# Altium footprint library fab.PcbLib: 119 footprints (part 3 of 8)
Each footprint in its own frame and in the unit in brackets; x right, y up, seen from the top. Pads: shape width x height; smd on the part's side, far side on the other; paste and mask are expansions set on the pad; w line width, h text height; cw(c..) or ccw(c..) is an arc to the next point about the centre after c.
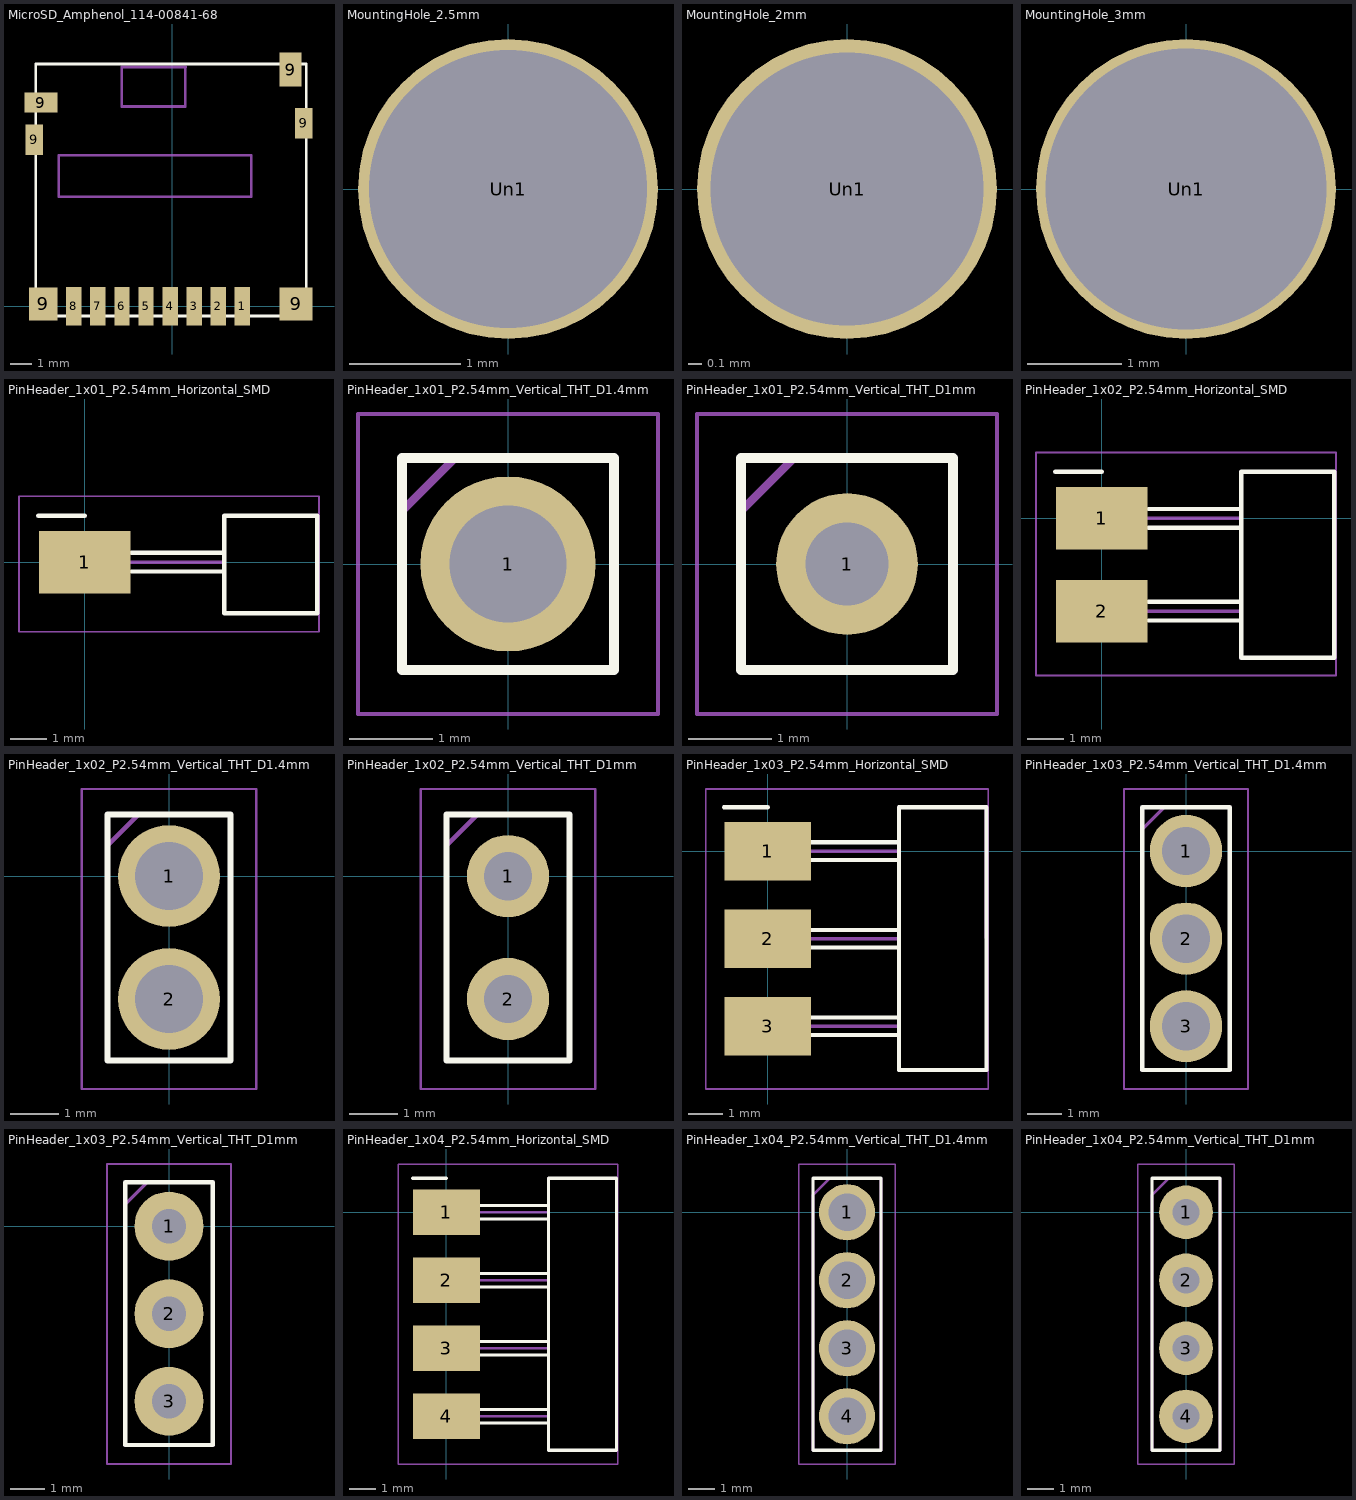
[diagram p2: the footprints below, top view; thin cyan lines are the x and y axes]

## MicroSD_Amphenol_114-00841-68 [mm]
pads (14):
  rect 0.7x1.75 smd: 1(3.2,0) 2(2.1,0) 3(1,0) 4(-0.1,0) 5(-1.2,0) 6(-2.3,0) 7(-3.4,0) 8(-4.5,0)
  rect 0.8x1.4 smd: 9(-6.3,7.6) 9(6,8.35)
  rect 1.5x0.9 smd: 9(-6,9.3)
  rect 1.3x1.5 smd: 9(-5.9,0.1)
  rect 1x1.55 smd: 9(5.4,10.8)
  rect 1.5x1.5 smd: 9(5.65,0.1)
F.SilkS:
  lines w0.12: -6.23,-0.45 -6.23,11.06 6.12,11.06 6.12,-0.45 -6.23,-0.45
F.Fab:
  lines w0.12: 0.6,10.92 0.6,9.12 -2.3,9.12 -2.3,10.92 0.61,10.92 ; -5.18,5 -5.18,6.89 3.61,6.89 3.61,5 -5.18,5
  text "%R" at -0.393,1.706 h1
  text "CLEAR" at -1.201,9.848 h0.5
  text "KEEP CLEAR" at -1.647,5.808 h0.5

## MountingHole_2.5mm [mm]
pads (1):
  round 2.7 hole 2.5: Un1(0,0)

## MountingHole_2mm [mm]
pads (1):
  round 2.2 hole 2: Un1(0,0)

## MountingHole_3mm [mm]
pads (1):
  round 3.2 hole 3: Un1(0,0)

## PinHeader_1x01_P2.54mm_Horizontal_SMD [mm]
pads (1):
  rect 2.5x1.7 smd: 1(0,0)
F.SilkS:
  lines w0.12: -1.27,1.27 0,1.27 ; 1.27,-0.254 3.81,-0.254 ; 1.27,0.254 3.81,0.254 ; 3.81,-1.397 6.35,-1.397 6.35,1.27 3.81,1.27 3.81,-1.397
F.CrtYd:
  lines w0.05: -1.8,-1.9 6.4,-1.9 6.4,1.8 -1.8,1.8 -1.8,-1.9
F.Fab:
  lines w0.1: -0.635,-0.254 -0.635,0.254 ; -0.635,0 3.81,0 ; 3.8,1.27 3.81,-1.4 6.36,-1.4 6.34,1.27 3.8,1.27
  text "%R" at 2.794,-0.393 h1

## PinHeader_1x01_P2.54mm_Vertical_THT_D1.4mm [mm]
pads (1):
  round 2.1 hole 1.4: 1(0,0)
F.SilkS:
  lines w0.12: -1.27,-1.27 1.27,-1.27 1.27,1.27 -1.27,1.27 -1.27,-1.27
F.CrtYd:
  lines w0.05: -1.8,-1.8 -1.8,1.8 1.8,1.8 1.8,-1.8 -1.8,-1.8
F.Fab:
  lines w0.1: -1.27,-1.27 1.27,-1.27 1.27,1.27 -0.635,1.27 -1.27,0.635 -1.27,-1.27
  text "%R" at 0.294,0.207 h1

## PinHeader_1x01_P2.54mm_Vertical_THT_D1mm [mm]
pads (1):
  rrect100% 1.7x1.7 hole 1: 1(0,0)
F.SilkS:
  lines w0.12: -1.27,-1.27 -1.27,1.27 1.27,1.27 1.27,-1.27 -1.27,-1.27
F.CrtYd:
  lines w0.05: -1.8,-1.8 1.8,-1.8 1.8,1.8 -1.8,1.8 -1.8,-1.8
F.Fab:
  lines w0.1: -1.27,-1.27 -1.27,0.635 -0.635,1.27 1.27,1.27 1.27,-1.27 -1.27,-1.27
  text "%R" at 0.294,0.207 h1

## PinHeader_1x02_P2.54mm_Horizontal_SMD [mm]
pads (2):
  rect 2.5x1.7 smd: 1(0,0) 2(0,-2.54)
F.SilkS:
  lines w0.12: -1.27,1.27 0,1.27 ; 1.27,-2.794 3.81,-2.794 ; 1.27,-2.286 3.81,-2.286 ; 1.27,-0.254 3.81,-0.254 ; 1.27,0.254 3.81,0.254 ; 3.81,-3.81 6.35,-3.81 6.35,1.27 3.81,1.27 3.81,-3.81
F.CrtYd:
  lines w0.05: -1.8,-4.3 6.4,-4.3 6.4,1.8 -1.8,1.8 -1.8,-4.3
F.Fab:
  lines w0.1: -0.635,-2.794 -0.635,-2.286 ; -0.635,-2.54 3.81,-2.54 ; -0.635,-0.254 -0.635,0.254 ; -0.635,0 3.81,0 ; 3.8,-3.81 6.35,-3.81 6.34,1.27 3.8,1.27 3.81,-3.81
  text "%R" at 2.894,-1.593 h1

## PinHeader_1x02_P2.54mm_Vertical_THT_D1.4mm [mm]
pads (2):
  round 2.1 hole 1.4: 1(0,0) 2(0,-2.54)
F.SilkS:
  lines w0.12: -1.27,-3.81 -1.27,1.27 1.27,1.27 1.27,-3.81 -1.27,-3.81
F.CrtYd:
  lines w0.05: -1.8,-4.4 1.8,-4.4 1.8,1.8 -1.8,1.8 -1.8,-4.4
F.Fab:
  lines w0.1: -1.27,-3.81 -1.27,0.635 -0.635,1.27 1.27,1.27 1.27,-3.81 -1.27,-3.81
  text "%R" at 0.294,-1.893 h1

## PinHeader_1x02_P2.54mm_Vertical_THT_D1mm [mm]
pads (2):
  rrect100% 1.7x1.7 hole 1: 1(0,0) 2(0,-2.54)
F.SilkS:
  lines w0.12: -1.27,-3.81 1.27,-3.81 1.27,1.27 -1.27,1.27 -1.27,-3.81
F.CrtYd:
  lines w0.05: -1.8,-4.4 -1.8,1.8 1.8,1.8 1.8,-4.4 -1.8,-4.4
F.Fab:
  lines w0.1: -1.27,-3.81 1.27,-3.81 1.27,1.27 -0.635,1.27 -1.27,0.635 -1.27,-3.81
  text "%R" at 0.294,-1.893 h1

## PinHeader_1x03_P2.54mm_Horizontal_SMD [mm]
pads (3):
  rect 2.5x1.7 smd: 1(0,0) 2(0,-2.54) 3(0,-5.08)
F.SilkS:
  lines w0.12: -1.27,1.27 0,1.27 ; 1.27,-5.334 3.81,-5.334 ; 1.27,-4.826 3.81,-4.826 ; 1.27,-2.794 3.81,-2.794 ; 1.27,-2.286 3.81,-2.286 ; 1.27,-0.254 3.81,-0.254 ; 1.27,0.254 3.81,0.254 ; 3.81,-6.35 3.81,1.27 6.35,1.27 6.35,-6.35 3.81,-6.35
F.CrtYd:
  lines w0.05: -1.8,-6.9 -1.8,1.8 6.4,1.8 6.4,-6.9 -1.8,-6.9
F.Fab:
  lines w0.1: -0.635,-5.334 -0.635,-4.826 ; -0.635,-5.08 3.81,-5.08 ; -0.635,-2.794 -0.635,-2.286 ; -0.635,-2.54 3.81,-2.54 ; -0.635,-0.254 -0.635,0.254 ; -0.635,0 3.81,0 ; 3.8,-6.35 6.35,-6.35 6.34,1.27 3.8,1.27 3.81,-6.35
  text "%R" at 2.694,-2.993 h1

## PinHeader_1x03_P2.54mm_Vertical_THT_D1.4mm [mm]
pads (3):
  round 2.1 hole 1.4: 1(0,0) 2(0,-2.54) 3(0,-5.08)
F.SilkS:
  lines w0.12: -1.27,-6.35 1.27,-6.35 1.27,1.27 -1.27,1.27 -1.27,-6.35
F.CrtYd:
  lines w0.05: -1.8,-6.9 -1.8,1.8 1.8,1.8 1.8,-6.9 -1.8,-6.9
F.Fab:
  lines w0.1: -1.27,-6.35 1.27,-6.35 1.27,1.27 -0.635,1.27 -1.27,0.635 -1.27,-6.35
  text "%R" at 0.294,-3.693 h1

## PinHeader_1x03_P2.54mm_Vertical_THT_D1mm [mm]
pads (3):
  rrect100% 2x2 hole 1: 1(0,0) 2(0,-2.54) 3(0,-5.08)
F.SilkS:
  lines w0.12: -1.27,-6.35 -1.27,1.27 1.27,1.27 1.27,-6.35 -1.27,-6.35
F.CrtYd:
  lines w0.05: -1.8,-6.9 1.8,-6.9 1.8,1.8 -1.8,1.8 -1.8,-6.9
F.Fab:
  lines w0.1: -1.27,-6.35 -1.27,0.635 -0.635,1.27 1.27,1.27 1.27,-6.35 -1.27,-6.35
  text "%R" at 0.294,-3.693 h1

## PinHeader_1x04_P2.54mm_Horizontal_SMD [mm]
pads (4):
  rect 2.5x1.7 smd: 1(0,0) 2(0,-2.54) 3(0,-5.08) 4(0,-7.62)
F.SilkS:
  lines w0.12: -1.27,1.27 0,1.27 ; 1.27,-7.874 3.81,-7.874 ; 1.27,-7.366 3.81,-7.366 ; 1.27,-5.334 3.81,-5.334 ; 1.27,-4.826 3.81,-4.826 ; 1.27,-2.794 3.81,-2.794 ; 1.27,-2.286 3.81,-2.286 ; 1.27,-0.254 3.81,-0.254 ; 1.27,0.254 3.81,0.254 ; 3.81,-8.89 6.35,-8.89 6.35,1.27 3.81,1.27 3.81,-8.89
F.CrtYd:
  lines w0.05: -1.8,-9.4 6.4,-9.4 6.4,1.8 -1.8,1.8 -1.8,-9.4
F.Fab:
  lines w0.1: -0.635,-7.874 -0.635,-7.366 ; -0.635,-7.62 3.81,-7.62 ; -0.635,-5.334 -0.635,-4.826 ; -0.635,-5.08 3.81,-5.08 ; -0.635,-2.794 -0.635,-2.286 ; -0.635,-2.54 3.81,-2.54 ; -0.635,-0.254 -0.635,0.254 ; -0.635,0 3.81,0 ; 3.8,-8.89 3.8,1.27 6.34,1.27 6.35,-8.89 3.8,-8.89
  text "%R" at 2.794,-4.293 h1

## PinHeader_1x04_P2.54mm_Vertical_THT_D1.4mm [mm]
pads (4):
  round 2.1 hole 1.4: 1(0,0) 2(0,-2.54) 3(0,-5.08) 4(0,-7.62)
F.SilkS:
  lines w0.12: -1.27,-8.89 -1.27,1.27 1.27,1.27 1.27,-8.89 -1.27,-8.89
F.CrtYd:
  lines w0.05: -1.8,-9.4 1.8,-9.4 1.8,1.8 -1.8,1.8 -1.8,-9.4
F.Fab:
  lines w0.1: -1.27,-8.89 -1.27,0.635 -0.635,1.27 1.27,1.27 1.27,-8.89 -1.27,-8.89
  text "%R" at 0.294,-5.473 h1

## PinHeader_1x04_P2.54mm_Vertical_THT_D1mm [mm]
pads (4):
  rrect100% 2x2 hole 1: 1(0,0) 2(0,-2.54) 3(0,-5.08) 4(0,-7.62)
F.SilkS:
  lines w0.12: -1.27,-8.89 1.27,-8.89 1.27,1.27 -1.27,1.27 -1.27,-8.89
F.CrtYd:
  lines w0.05: -1.8,-9.4 -1.8,1.8 1.8,1.8 1.8,-9.4 -1.8,-9.4
F.Fab:
  lines w0.1: -1.27,-8.89 1.27,-8.89 1.27,1.27 -0.635,1.27 -1.27,0.635 -1.27,-8.89
  text "%R" at 0.294,-5.473 h1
